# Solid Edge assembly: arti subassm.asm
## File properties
Author: Robert a Rhodes jr
Template: Normal.asm
Last saved by: CADCIM
Revision: 15
Application: Solid Edge
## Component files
rod bush lower.par
rod bush upper.par
articulated rod.par
piston.par
piston pin.par
piston pin plug.par
piston ring.par
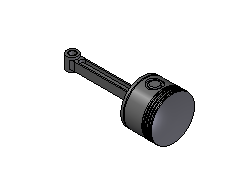
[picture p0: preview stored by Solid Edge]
